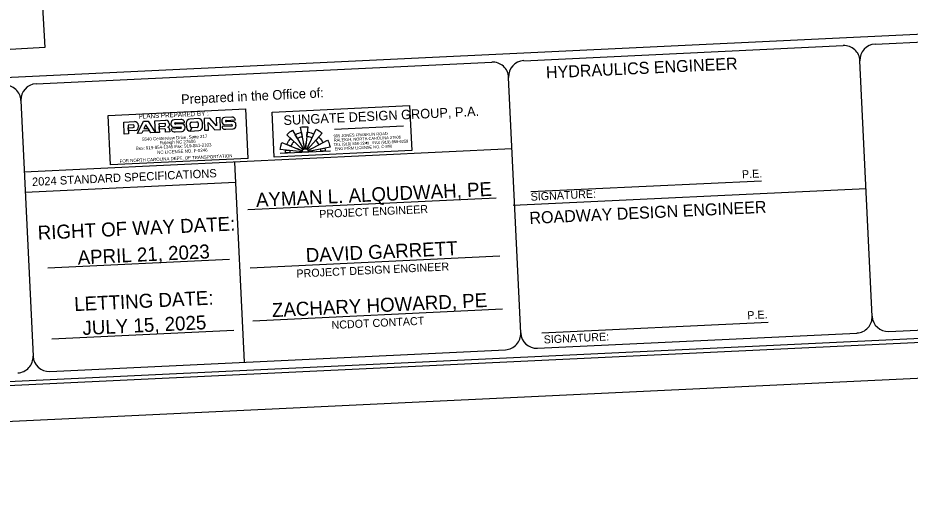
# Model space of a CAD drawing. Extents: x 2170913 to 2188101, y 74009 to 87693.
# Drawn here: x 2178181 to 2182226, y 74009 to 76166 of the extents above; entities that cross this region are included whole.
import ezdxf

# ---------------------------------------------------------------- set-up
doc = ezdxf.new("R2010")
doc.units = 0
for name, color, linetype in [('CTL Primary Horizontal and Vertical CELL', 7, 'Continuous'), ('CTL Primary Horizontal and Vertical Cogo Comment', 7, 'Continuous'), ('CTL Primary Horizontal Cogo Comment', 7, 'Continuous'), ('CTL Primary Horizontal Cogo Number', 7, 'Continuous'), ('Exist Other Culture Sign Cogo Point CELL', 7, 'Continuous'), ('Exist Structure Minor Pipes HDPE 30 Inch', 7, 'Continuous'), ('Exist Utilities Other Pole CELL', 7, 'Continuous')]:
    doc.layers.add(name, color=color, linetype=linetype)

msp = doc.modelspace()

# ---------------------------------------------------------------- linework, layer by layer
at = {"layer": 'CTL Primary Horizontal and Vertical CELL'}
msp.add_lwpolyline([(2183118, 82562.2), (2170912.8, 81981.8), (2171291.9, 74009.3), (2183497.2, 74589.8)], close=True, dxfattribs=at)
at = {"layer": 'CTL Primary Horizontal and Vertical Cogo Comment'}
for p, q in [((2178591.4, 75723.6), (2179214.9, 75753.1)), ((2178602.1, 75498.9), (2178591.4, 75723.6)), ((2179225.5, 75528.5), (2179214.9, 75753.1)), ((2178727.9, 75678.1), (2178728.2, 75672.8)), ((2178850.7, 75678.6), (2178850.4, 75684.7)), ((2178867.9, 75687.3), (2178868.3, 75679.1)), ((2178874.8, 75686.2), (2178874.9, 75684)), ((2178920.5, 75705), (2178889.6, 75703.6)), ((2178895.2, 75690), (2178937, 75691.9)), ((2178925.4, 75684.6), (2178895.6, 75683.2)), ((2178944.8, 75687.7), (2178945.7, 75669.6)), ((2178998.7, 75708.7), (2178961, 75706.9)), ((2178963.9, 75673), (2178963.3, 75686.8)), ((2178968.3, 75692.7), (2178992.9, 75693.9)), ((2178998.4, 75688.5), (2178999.1, 75674.6)), ((2179018.8, 75674.5), (2179018.1, 75689.7)), ((2179105.6, 75697.1), (2179105.7, 75694.9)), ((2179120.1, 75680.7), (2179150.6, 75681.4)), ((2179151.3, 75716), (2179120.4, 75714.5)), ((2179126, 75700.9), (2179167.8, 75702.9)), ((2179156.2, 75695.6), (2179126.4, 75694.2)), ((2179170.3, 75677.7), (2179170.1, 75682)), ((2178709.2, 75673), (2178709.1, 75676.2)), ((2178889.3, 75669.7), (2178919.7, 75670.5)), ((2178894.2, 75649.4), (2178926, 75650.9)), ((2178939.5, 75666.8), (2178939.3, 75671.1)), ((2178962.9, 75652.6), (2178969.4, 75667.5)), ((2178962.9, 75652.6), (2179002, 75654.5)), ((2179125, 75660.3), (2179156.8, 75661.8)), ((2179225.5, 75528.5), (2178602.1, 75498.9))]:
    msp.add_line(p, q, dxfattribs=at)
for points in [[(2178704.9, 75680.3), (2178680.9, 75679.1), (2178681.5, 75666.7), (2178682.5, 75652.9), (2178683.1, 75639.4), (2178663.9, 75638.5), (2178661.3, 75692.8), (2178710.5, 75695.1)], [(2178848, 75687), (2178821.1, 75685.7), (2178821.7, 75673.7), (2178822.3, 75660.5), (2178823, 75646), (2178805.1, 75645.2), (2178802.5, 75699.4), (2178852.9, 75701.8)], [(2178712.4, 75654.3), (2178682.5, 75652.9), (2178681.5, 75666.7), (2178704.8, 75667.8)], [(2178869.2, 75659.9), (2178869.8, 75648.2), (2178851.5, 75647.4), (2178850.9, 75659.8), (2178848.5, 75661.8), (2178822.3, 75660.5), (2178821.7, 75673.7), (2178847.5, 75674.9)], [(2178920.1, 75663.8), (2178876.6, 75661.7), (2178876.7, 75660.6)], [(2178994.1, 75668.7), (2178969.4, 75667.5), (2178962.9, 75652.6), (2179002, 75654.5)], [(2179150.9, 75674.7), (2179107.5, 75672.7), (2179107.5, 75671.6)]]:
    msp.add_lwpolyline(points, dxfattribs=at)
for points in [[(2178723.4, 75641.3), (2178750.7, 75697), (2178772.4, 75698), (2178804.5, 75645.1), (2178784.2, 75644.2), (2178761.7, 75681.2), (2178753, 75663.3), (2178772, 75664.2), (2178778.8, 75653.2), (2178747.6, 75651.7), (2178743.1, 75642.2)], [(2179025.4, 75710), (2179028, 75655.7), (2179046.4, 75656.6), (2179044.7, 75691.7), (2179074.6, 75657.9), (2179100.5, 75659.1), (2179098, 75713.4), (2179080.3, 75712.6), (2179082, 75676.4), (2179051.7, 75711.2)]]:
    msp.add_lwpolyline(points, close=True, dxfattribs=at)
for centre, major_axis, ratio, start_param, end_param in [((2178705.1, 75676), (-0.2, 4.26), 0.93676, 4.712389, 6.283185), ((2178711.3, 75677.3), (-0.8, 17.7), 0.93676, 4.712389, 6.283185), ((2178847.4, 75678.4), (-0.17, 3.55), 0.934072, 3.141593, 4.712389), ((2178848.1, 75684.5), (-0.12, 2.48), 0.934072, 4.712389, 6.283185), ((2178853.6, 75686.6), (-0.7, 15.3), 0.934072, 4.712389, 6.283185), ((2178859.7, 75678.7), (-0.44, 9.23), 0.934072, 3.34512, 4.712389), ((2178890.4, 75686.9), (-0.8, 16.7), 0.934072, 0, 1.570796), ((2178888.9, 75684.6), (0.7, -14.9), 0.934072, 4.712389, 6.260753), ((2178895.4, 75686.6), (-0.16, 3.37), 0.934072, 0, 3.141593), ((2178921.5, 75682), (-1.1, 23.1), 0.934072, 5.902203, 6.283185), ((2178926.1, 75670.4), (-0.7, 14.2), 0.934072, 4.712389, 6.283185), ((2178924.4, 75691), (-0.6, 13.5), 0.934072, 4.738699, 5.901866), ((2178961.9, 75688.5), (-0.9, 18.5), 0.924824, 0, 1.570796), ((2178968.5, 75687), (0.27, -5.68), 0.924824, 3.141593, 4.712389), ((2178993.1, 75688.2), (-0.27, 5.68), 0.924824, 4.712389, 6.283185), ((2178999.7, 75688.9), (-0.9, 19.9), 0.924824, 4.712389, 6.283185), ((2179121.2, 75697.8), (-0.8, 16.7), 0.934072, 0, 1.570796), ((2179119.7, 75695.6), (0.7, -14.9), 0.934072, 4.712389, 6.260753), ((2179126.2, 75697.5), (-0.16, 3.37), 0.934072, 0, 3.141593), ((2179150.7, 75678.1), (-0.16, 3.37), 0.934072, 3.141593, 6.283185), ((2179152.4, 75692.9), (-1.1, 23.1), 0.934072, 5.902203, 6.283185), ((2179156.9, 75681.4), (-0.7, 14.2), 0.934072, 4.712389, 6.283185), ((2179156.1, 75677.1), (-0.7, 15.3), 0.934072, 3.141593, 4.712389), ((2179155.2, 75701.9), (-0.6, 13.5), 0.934072, 4.738699, 5.901866), ((2178704.6, 75672.8), (-0.24, 4.97), 0.93676, 3.141593, 4.712389), ((2178711.6, 75672), (-0.8, 17.7), 0.93676, 3.141593, 4.712389), ((2178859.2, 75659.4), (-0.5, 10.6), 0.934072, 4.712389, 5.969561), ((2178887, 75661.1), (0.5, -11), 0.934072, 4.712389, 5.988639), ((2178892.5, 75684.9), (-1.7, 35.5), 0.934072, 2.847261, 3.141593), ((2178919.9, 75667.1), (-0.16, 3.37), 0.934072, 3.141593, 6.283185), ((2178925.3, 75666.1), (-0.7, 15.3), 0.934072, 3.141593, 4.712389), ((2178962.1, 75670.4), (0.8, -17.7), 0.924824, 4.712389, 6.283185), ((2178969.2, 75673.2), (0.27, -5.68), 0.924824, 4.712389, 6.283185), ((2178993.8, 75674.4), (-0.27, 5.68), 0.924824, 3.141593, 4.712389), ((2179001.1, 75673.6), (-0.9, 19.2), 0.924824, 3.141593, 4.712389), ((2179117.8, 75672), (0.5, -11), 0.934072, 4.712389, 5.988639), ((2179123.3, 75695.8), (-1.7, 35.5), 0.934072, 2.847261, 3.141593)]:
    msp.add_ellipse(centre, major_axis=major_axis, ratio=ratio, start_param=start_param, end_param=end_param, dxfattribs=at)
at = {"layer": 'CTL Primary Horizontal Cogo Comment'}
msp.add_lwpolyline([(2171378.4, 74176.5), (2183456.8, 74750.8), (2183093.1, 82397.9), (2171014.8, 81823.6)], close=True, dxfattribs=at)
at = {"layer": 'CTL Primary Horizontal Cogo Number'}
for p, q in [((2172899.3, 75647.6), (2183191.1, 76137)), ((2182067.8, 76047.3), (2183192.8, 76100.8)), ((2180474.9, 75971.5), (2181922.8, 76040.4)), ((2178264.4, 75866.4), (2180330, 75964.6)), ((2182053.9, 74811.7), (2181998.7, 75971.3)), ((2180461.1, 74735.9), (2180405.9, 75895.5)), ((2178195.3, 75790.5), (2178250.5, 74630.8)), ((2180421.3, 75571.2), (2178210.8, 75466.1)), ((2179164.2, 75511.5), (2179207.4, 74603.7)), ((2179168.6, 75419), (2178215.2, 75373.7)), ((2178893.9, 75406), (2178893.9, 75406)), ((2180506.8, 75377.4), (2181552.3, 75427.2)), ((2180427, 75315.6), (2182026.3, 75391.7)), ((2179224.5, 75296.6), (2180349, 75350)), ((2179234.6, 75032.3), (2180367, 75086.2)), ((2179141.6, 75070.2), (2178317.2, 75031)), ((2178729.2, 75050.5), (2178729.2, 75050.5)), ((2179246, 74791.9), (2180378.5, 74845.8)), ((2179159.9, 74747.1), (2178335.4, 74707.9)), ((2180557.3, 74736.5), (2181582.8, 74785.2))]:
    msp.add_line(p, q, dxfattribs=at)
for points in [[(2182129.9, 74742.7), (2183254.9, 74796.2)], [(2172566.2, 74251.5), (2183292.9, 74761.6)], [(2180537, 74666.9), (2181984.9, 74735.8)], [(2178326.4, 74561.8), (2180392, 74659.9)]]:
    msp.add_lwpolyline(points, dxfattribs=at)
for centre, start, end in [((2182071.2, 75974.8), 92.7227, 182.7227), ((2181926.3, 75967.9), 2.7227, 92.7227), ((2180333.4, 75892.5), 2.7227, 92.7227), ((2180478.4, 75899.4), 92.7227, 182.7227), ((2178122.9, 75787.3), 2.7227, 92.7227), ((2178267.8, 75794.2), 92.7227, 182.7227), ((2181981.4, 74808.7), 272.7227, 2.7227), ((2182126.4, 74815.6), 182.7227, 272.7227), ((2180388.6, 74732.8), 272.7227, 2.7227), ((2180533.5, 74739.7), 182.7227, 272.7227), ((2178178, 74627.7), 272.7227, 2.7227), ((2178323, 74634.6), 182.7227, 272.7227)]:
    msp.add_arc(centre, 72.6, start, end, dxfattribs=at)
at = {"layer": 'Exist Structure Minor Pipes HDPE 30 Inch'}
msp.add_lwpolyline([(2174631.9, 78625), (2175899.9, 78682), (2175882.4, 79071.3), (2176656, 79297.5), (2177391.1, 79031.4), (2178152.3, 78655.2), (2178303.3, 76031.7), (2174802.3, 75830.2), (2174781.3, 76195.1), (2174799.2, 76231.4), (2174723.3, 76523.2)], close=True, dxfattribs=at)
at = {"layer": 'Exist Utilities Other Pole CELL'}
for p, q in [((2179616.9, 75660.9), (2179930.1, 75675.7)), ((2179448.8, 75618.1), (2179448.8, 75618.1)), ((2179481.7, 75571.9), (2179476.6, 75597.6)), ((2179486, 75572.1), (2179488.6, 75598.2)), ((2179514.7, 75621.2), (2179514.7, 75621.2)), ((2179370.1, 75552), (2179599, 75562.8)), ((2179403.9, 75565.4), (2179403.9, 75565.4)), ((2179469.8, 75558.8), (2179443.7, 75561.5)), ((2179470.9, 75563), (2179446.6, 75573.1)), ((2179453.3, 75570.4), (2179453.3, 75570.4)), ((2179454.3, 75585.1), (2179473.6, 75567.4)), ((2179477, 75570.1), (2179463.6, 75592.6)), ((2179490.9, 75570.8), (2179502.1, 75594.5)), ((2179512, 75587.8), (2179494.5, 75568.4)), ((2179497.6, 75564.3), (2179520.8, 75576.6)), ((2179511, 75571.4), (2179497.6, 75564.3)), ((2179499.1, 75560.2), (2179524.8, 75565.3))]:
    msp.add_line(p, q, dxfattribs=at)
for points in [[(2179334, 75738.2), (2179957.5, 75767.8), (2179967.1, 75563.6), (2179343.7, 75534.1)], [(2179473.6, 75567.4), (2179400.1, 75634.8), (2179404.6, 75639.5), (2179409.7, 75644.2), (2179414.8, 75648.3), (2179420.4, 75652.4), (2179426, 75655.9), (2179477, 75570.1)], [(2179438.3, 75635.2), (2179442.5, 75637.6), (2179449, 75640.6), (2179455.9, 75643.3), (2179462.2, 75645.1), (2179467.1, 75646.2), (2179471, 75626.5), (2179466.3, 75625.4), (2179462, 75624.1), (2179457.5, 75622.4), (2179452.8, 75620.3), (2179448.6, 75617.9)], [(2179481.7, 75571.9), (2179462.4, 75669.8), (2179468.7, 75670.9), (2179475.8, 75671.6), (2179481.8, 75671.9), (2179489.2, 75671.9), (2179496, 75671.4), (2179486, 75572.1)], [(2179490.9, 75570.8), (2179533.5, 75661), (2179540.3, 75657.5), (2179547.8, 75653), (2179552.5, 75649.7), (2179557, 75646.2), (2179561.3, 75642.5), (2179494.5, 75568.4)], [(2179493.6, 75647.5), (2179499.1, 75646.7), (2179505.3, 75645.5), (2179511.5, 75643.8), (2179517.2, 75641.8), (2179523.2, 75639.2), (2179514.7, 75621.1), (2179511.2, 75622.6), (2179506.7, 75624.2), (2179500.3, 75626), (2179495.8, 75626.9), (2179491.6, 75627.5)], [(2179469.8, 75558.8), (2179370.5, 75568.8), (2179371.3, 75574.8), (2179373, 75583.6), (2179374.4, 75589), (2179376.6, 75595.9), (2179378.6, 75601.1), (2179470.9, 75563)], [(2179400.9, 75591.9), (2179403.2, 75597.1), (2179405.3, 75601.1), (2179408.1, 75605.9), (2179410.9, 75610), (2179414, 75614.1), (2179417.8, 75618.6), (2179432.6, 75605), (2179429.4, 75601.2), (2179426.9, 75597.9), (2179424.6, 75594.3), (2179422.3, 75590.3), (2179420.7, 75587.1), (2179419.4, 75584.2)], [(2179497.6, 75564.2), (2179585.8, 75611), (2179588.2, 75606.3), (2179590.7, 75600.7), (2179593.1, 75594.3), (2179594.7, 75589.1), (2179597, 75579.5), (2179499.1, 75560.2)], [(2179545.2, 75624.6), (2179549, 75620.9), (2179552.8, 75616.9), (2179556.3, 75612.6), (2179560.6, 75606.4), (2179564.6, 75599.7), (2179546.8, 75590.3), (2179544.3, 75594.7), (2179541, 75599.6), (2179538.2, 75603), (2179535.6, 75605.9), (2179531.7, 75609.7)], [(2179394.1, 75553.1), (2179394, 75557), (2179394.1, 75561.6), (2179394.5, 75566.4), (2179414.5, 75564.4), (2179414.2, 75561), (2179414.1, 75557.5), (2179414.2, 75554)], [(2179469.8, 75556.7), (2179469.8, 75557.8), (2179469.8, 75558.8), (2179470.3, 75561.2), (2179470.9, 75563), (2179471.5, 75564.4), (2179472.3, 75565.7), (2179473, 75566.6), (2179473.6, 75567.4), (2179475.3, 75568.9), (2179477, 75570.1), (2179478.2, 75570.7), (2179479.6, 75571.3), (2179480.8, 75571.7), (2179481.7, 75571.9), (2179483.9, 75572.2), (2179486, 75572.1), (2179487.3, 75571.9), (2179488.4, 75571.7), (2179489.6, 75571.3), (2179490.9, 75570.8), (2179492.8, 75569.7), (2179494.5, 75568.4), (2179495.3, 75567.5), (2179496.2, 75566.5), (2179496.9, 75565.6), (2179497.6, 75564.3), (2179498.6, 75562.2), (2179499.1, 75560.2), (2179499.3, 75559.1), (2179499.3, 75558.1)], [(2179573.4, 75574.9), (2179574.4, 75568), (2179575, 75561.8), (2179554.9, 75560.7), (2179554.5, 75565.8), (2179553.7, 75571)]]:
    msp.add_lwpolyline(points, close=True, dxfattribs=at)
for start, end in [(2.7111, 182.7111), (182.7111, 2.7111)]:
    msp.add_arc((2179763, 75598.6), 0.639, start, end, dxfattribs=at)

# ---------------------------------------------------------------- texts
at = {"layer": 'CTL Primary Horizontal and Vertical Cogo Comment'}
for s, height, rotation, p in [('PLANS PREPARED BY : ', 20.5, 2.7102, (2178729.8, 75708.1)), ('Bus: 919-854-1345 Fax: 919-851-2103', 14.402, 2.7111, (2178717, 75566.7)), ('5540 Centerview Drive, Suite 217', 14.402, 2.7111, (2178744.8, 75607.6)), ('Raleigh NC 27606', 14.402, 2.7111, (2178825.4, 75591.6)), ('NC LICENSE NO. F-0246', 14.402, 2.7111, (2178813.5, 75548.2)), ('FOR NORTH CAROLINA DEPT. OF TRANSPORTATION', 14.402, 2.7111, (2178643.6, 75509))]:
    msp.add_text(s, height=height, rotation=rotation, dxfattribs=at).set_placement(p)
at = {"layer": 'CTL Primary Horizontal Cogo Number'}
for s, height, p in [(' HYDRAULICS ENGINEER', 54.42, (2180556.5, 75890)), ('Prepared in the Office of:', 43.531, (2178922.5, 75774.5)), ('2024 STANDARD SPECIFICATIONS', 37.731, (2178246.4, 75403.2)), ('P.E.', 36.28, (2181464.9, 75437.9)), ('SIGNATURE:', 36.28, (2180506.7, 75336.1)), ('PROJECT ENGINEER', 36.276, (2179548.6, 75257.6)), ('ROADWAY DESIGN ENGINEER', 54.415, (2180501.7, 75230.7)), ('RIGHT OF WAY DATE: ', 63.488, (2178273, 75158.9)), ('PROJECT DESIGN ENGINEER', 36.276, (2179445.2, 74987.4)), ('LETTING DATE:', 63.488, (2178438.4, 74835.2)), ('P.E.', 36.28, (2181488.9, 74798.3)), ('NCDOT CONTACT', 36.276, (2179604.2, 74754)), ('SIGNATURE:', 36.28, (2180566.1, 74688.3))]:
    msp.add_text(s, height=height, rotation=2.7227, dxfattribs=at).set_placement(p)
at = {"layer": 'Exist Other Culture Sign Cogo Point CELL'}
for s, p in [('AYMAN L. ALQUDWAH, PE', (2179262.3, 75307.8)), ('DAVID GARRETT', (2179488.1, 75057.2)), ('APRIL 21, 2023', (2178453.9, 75046.7)), ('ZACHARY HOWARD, PE', (2179334.7, 74807.9)), ('JULY 15, 2025', (2178475.9, 74726.8))]:
    msp.add_text(s, height=63.49, rotation=2.7227, dxfattribs=at).set_placement(p)
at = {"layer": 'Exist Utilities Other Pole CELL'}
for s, height, p in [('SUNGATE DESIGN GROUP, P.A.', 43.278, (2179386.5, 75679.4)), ('905 JONES FRANKLIN ROAD', 13.006, (2179613.1, 75623.3)), ('TEL (919) 859-2243   FAX (919) 859-6258', 13.006, (2179613.7, 75584.5)), ('RALEIGH, NORTH CAROLINA 27606', 13.006, (2179614.1, 75604.2)), ('ENG FIRM LICENSE NO. C-890', 13.006, (2179618.2, 75564.9))]:
    msp.add_text(s, height=height, rotation=2.7111, dxfattribs=at).set_placement(p)

doc.saveas('drawing.dxf')
